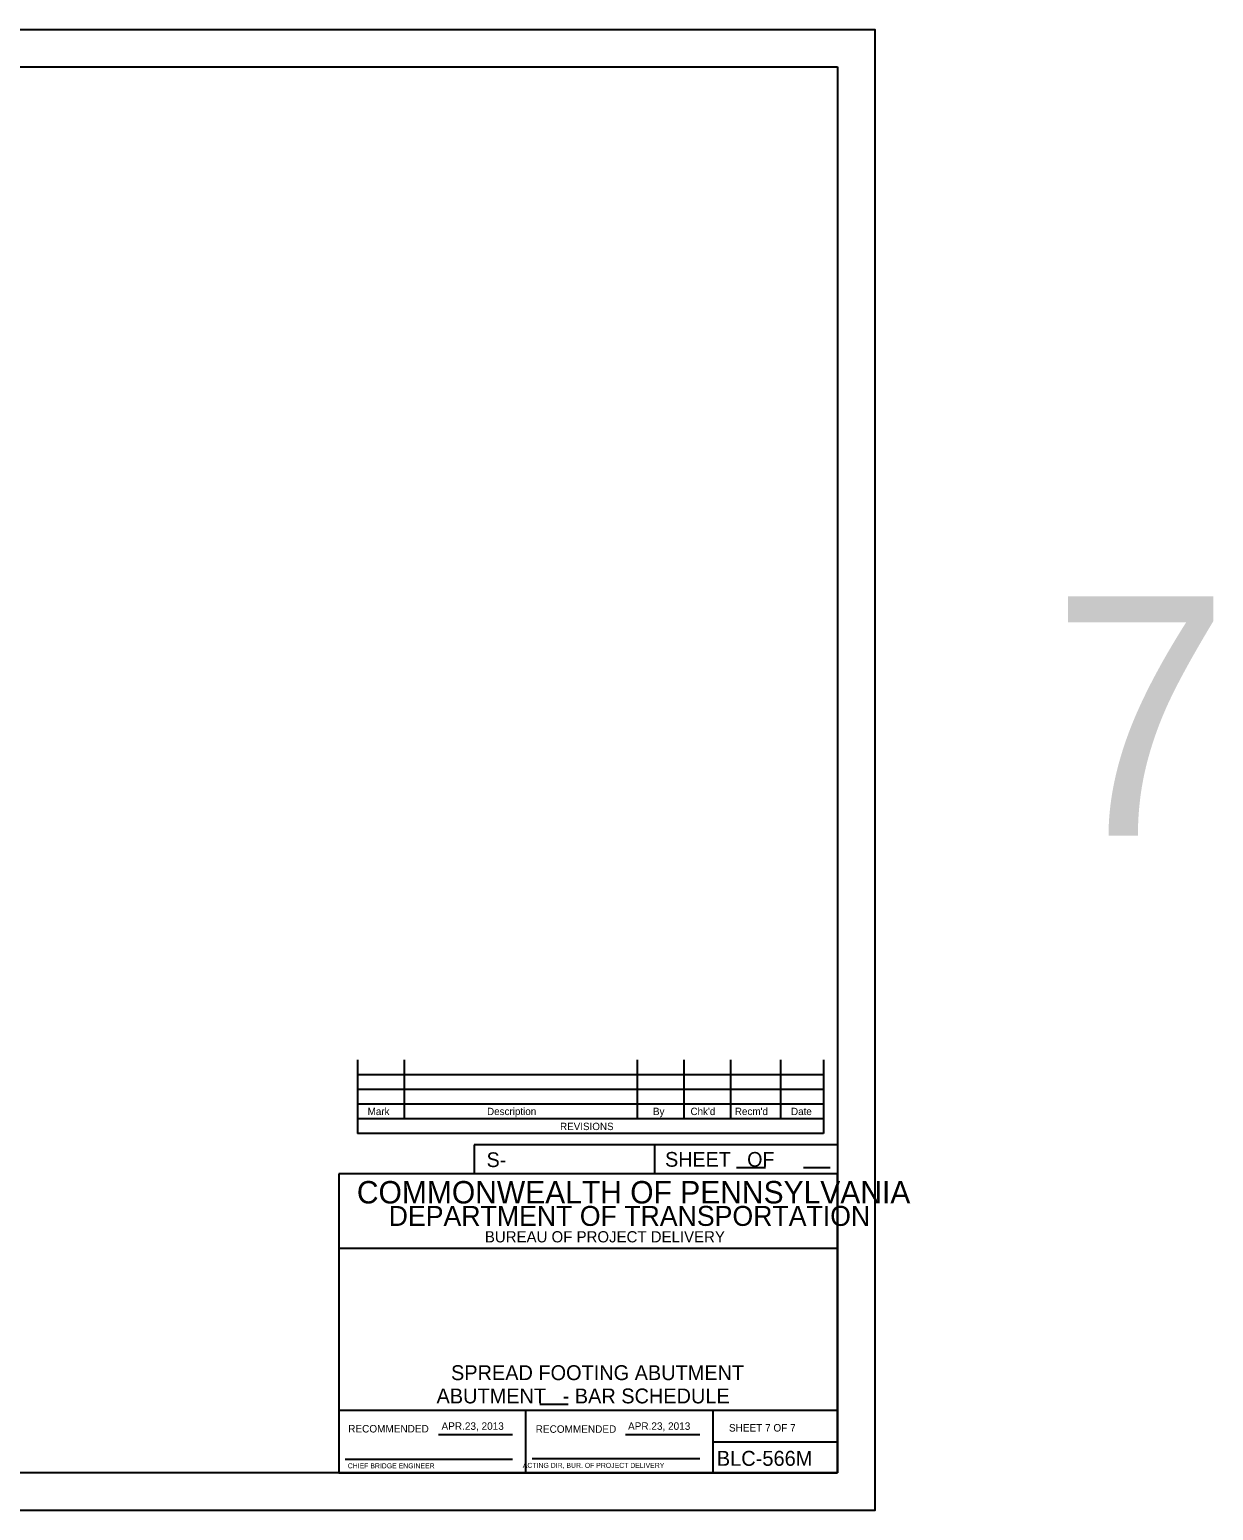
# Model space of a CAD drawing. Extents: x 638255 to 640306, y 296059 to 298435.
# Drawn here: x 639778 to 640253, y 296059 to 296653 of the extents above; entities that cross this region are included whole.
import ezdxf

# ---------------------------------------------------------------- set-up
doc = ezdxf.new("R2010")
doc.units = 0
for name, color, linetype in [('2', 7, 'Continuous'), ('4', 7, 'Continuous'), ('PLT-BNDY', 7, 'Continuous')]:
    doc.layers.add(name, color=color, linetype=linetype)

msp = doc.modelspace()

# ---------------------------------------------------------------- linework, layer by layer
at = {"layer": '2'}
for p, q in [((639316.46, 296638.46), (640102.46, 296638.46)), ((640102.46, 296638.46), (640102.46, 296074.46)), ((639909.92, 296240.15), (639909.92, 296210.62)), ((639928.62, 296240.15), (639928.62, 296216.53)), ((640022.13, 296240.15), (640022.13, 296216.53)), ((640040.83, 296240.15), (640040.83, 296216.53)), ((640059.53, 296240.15), (640059.53, 296216.53)), ((640079.59, 296240.15), (640079.59, 296216.53)), ((640096.94, 296240.15), (640096.94, 296210.62)), ((640096.94, 296234.24), (639909.92, 296234.24)), ((640096.94, 296228.34), (639909.92, 296228.34)), ((640096.94, 296222.43), (639909.92, 296222.43)), ((640096.94, 296216.53), (639909.92, 296216.53)), ((640096.94, 296210.62), (639909.92, 296210.62)), ((640102.46, 296206.11), (639956.78, 296206.11)), ((639956.78, 296206.11), (639956.78, 296194.46)), ((640029.09, 296206.11), (640029.09, 296194.46)), ((640102.46, 296194.46), (639902.46, 296194.46)), ((639902.46, 296194.46), (639902.46, 296074.46)), ((640061.95, 296197), (640073.6, 296197)), ((640088.83, 296197), (640099.56, 296197)), ((640102.46, 296074.46), (640102.46, 296194.46)), ((640102.46, 296164.46), (639902.46, 296164.46)), ((640102.46, 296099.46), (639902.46, 296099.46)), ((639977.46, 296074.46), (639977.46, 296099.46)), ((640052.46, 296099.46), (640052.46, 296074.46)), ((639942.42, 296089.96), (639972.19, 296089.96)), ((640017.42, 296089.96), (640047.33, 296089.96)), ((640052.46, 296086.96), (640102.46, 296086.96)), ((639904.96, 296079.96), (639972.19, 296079.96)), ((639980.08, 296080.33), (640047.33, 296080.33)), ((640102.46, 296074.46), (639316.46, 296074.46)), ((639902.46, 296074.46), (640102.46, 296074.46))]:
    msp.add_line(p, q, dxfattribs=at)
at = {"layer": '4'}
msp.add_line((639983.13, 296102.08), (639994.5, 296102.08), dxfattribs=at)
at = {"layer": 'PLT-BNDY'}
msp.add_lwpolyline([(639276.46, 296653.46), (640117.46, 296653.46), (640117.46, 296059.46), (639276.46, 296059.46)], close=True, dxfattribs=at)

# ---------------------------------------------------------------- texts
at = {"layer": '2'}
for s, height, p in [('Mark', 2.952, (639914.02, 296218.03)), ('Description', 2.9523, (639961.92, 296218.03)), ('By', 2.952, (640028.49, 296218.03)), ("Chk'd", 2.952, (640043.52, 296218.03)), ("Recm'd", 2.953, (640061.33, 296218.03)), ('Date', 2.952, (640083.86, 296218.03)), ('REVISIONS', 2.952, (639991.2, 296212.01)), ('S-', 5.905, (639961.73, 296197.17)), ('SHEET   OF', 5.907, (640033.35, 296197.31)), ('COMMONWEALTH OF PENNSYLVANIA', 9, (639909.71, 296182.58)), ('DEPARTMENT OF TRANSPORTATION', 8.0002, (639922.46, 296173.58)), ('BUREAU OF PROJECT DELIVERY', 4.5, (639961.05, 296166.96)), ('ABUTMENT   - BAR SCHEDULE', 5.9728, (639941.66, 296102.37)), ('APR.23, 2013', 3, (639943.67, 296091.77)), ('APR.23, 2013', 3, (640018.48, 296091.77)), ('SHEET 7 OF 7', 3, (640058.97, 296091.08)), ('BLC-566M', 6, (640054.08, 296077.33)), ('CHIEF BRIDGE ENGINEER', 2.0002, (639906.05, 296076.33)), ('  ACTING DIR, BUR. OF PROJECT DELIVERY', 2.0002, (639974.73, 296076.51))]:
    msp.add_text(s, height=height, dxfattribs=at).set_placement(p)
for p in [(639906.23, 296090.71), (639981.44, 296090.58)]:
    msp.add_text('RECOMMENDED', height=3, rotation=360, dxfattribs=at).set_placement(p)
at = {"layer": '4'}
for s, height, p in [('7', 96, (640188.35, 296330.15)), ('SPREAD FOOTING ABUTMENT', 5.9728, (639947.47, 296111.71))]:
    msp.add_text(s, height=height, dxfattribs=at).set_placement(p)

doc.saveas('drawing.dxf')
